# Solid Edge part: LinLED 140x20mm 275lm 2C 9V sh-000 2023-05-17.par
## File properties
Author: jaroslaw.przewlocki
Template: iso metric part.par
Last saved by: jaroslaw.przewlocki
Revision: 2
Application: Solid Edge
Gęstość: 0,000 kg/m^3
Dokładność: 0,990
Username: jaroslaw.przewlocki
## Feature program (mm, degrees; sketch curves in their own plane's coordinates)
body "unnamed Body 1"
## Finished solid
Body 1: solid body, 662 faces, 1696 edges, 1072 vertices.
  Faces by surface: plane 360, cylinder 146, torus 64, cone 50, spline 26, sphere 16
  Edges by curve: line 1056, curve on surface 356, circle 182, ellipse 66, spline 36
Bounding box of the edges (mm; curved faces can reach further): 139.600 x 20.000 x 4.450, from (-69.8, -10, -1) to (69.8, 10, 3.45).
Cylindrical faces by radius (mm): R0.2 x46, R0.2169 x6, R0.25 x20, R0.3373 x6, R0.4 x8, R0.4006 x2, R0.4008 x2, R0.525 x2, R0.6 x20, R1 x12, R1.1 x4, R1.1989 x2, R1.199 x2, R1.2 x10, R2.15 x4
Conical faces (half-angle, radius in mm at the cone's reference point): 0.398 deg R1.1964 x2, 0.4493 deg R1.1964 x2, 0.4746 deg R1.1948 x2, 0.4758 deg R1.1948 x2, 0.5 deg R0.5056 x4, 0.5 deg R1.0082 x4, 1 deg R0.5511 x2, 10 deg R0.2132 x4, 10 deg R0.4132 x4, 16.0099 deg R1.1053 x2, 16.1249 deg R1.1279 x2, 18.8604 deg R1.0669 x4, 19.5041 deg R0.5138 x2, 19.8244 deg R0.5099 x2, 27.363 deg R0.6214 x2, 40.6434 deg R0.5161 x2, 43.3309 deg R0.4892 x2, 45 deg R0.575 x2, 45 deg R0.625 x4
Toroidal faces (ring radius, tube radius in mm): R0.0958 r0.3997 x4, R0.1076 r0.4 x2, R0.1101 r0.4001 x2, R0.1217 r0.4 x2, R0.1234 r0.4 x2, R0.1626 r0.228 x2, R0.1634 r0.2287 x2, R0.3287 r0.2001 x2, R0.3684 r0.2151 x2, R0.3703 r0.4 x2, R0.3818 r0.2 x4, R0.4166 r0.3983 x2, R0.5981 r0.197 x2, R0.5982 r0.197 x2, R0.6009 r0.3968 x2, R0.6009 r0.3969 x2, R0.6227 r0.2 x2, R0.6235 r0.2 x2, R0.8 r0.2 x4, R0.8522 r0.3 x2, R0.9002 r0.2 x2, R0.9018 r0.2 x2, R0.9197 r0.223 x2, R0.9365 r0.2 x2, R0.9663 r0.2263 x2, R0.9665 r0.2263 x2, R1.429 r1.2 x2, R1.8741 r0.2175 x2, R1.9007 r0.2 x2
Spherical faces by radius (mm): R0.2 x12, R0.6 x4
Planar faces by outward normal: +x 38, +y 41, +z 52, -x 38, -y 41, -z 9, oblique 141
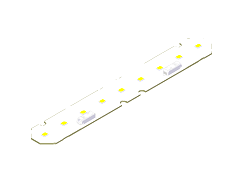
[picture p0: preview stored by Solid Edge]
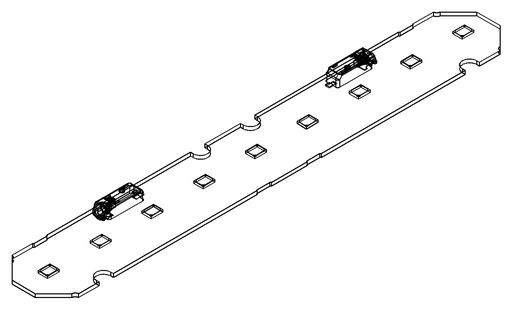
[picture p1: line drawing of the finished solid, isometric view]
